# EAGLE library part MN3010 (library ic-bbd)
Dual 512-Stage Lo Noise BBD
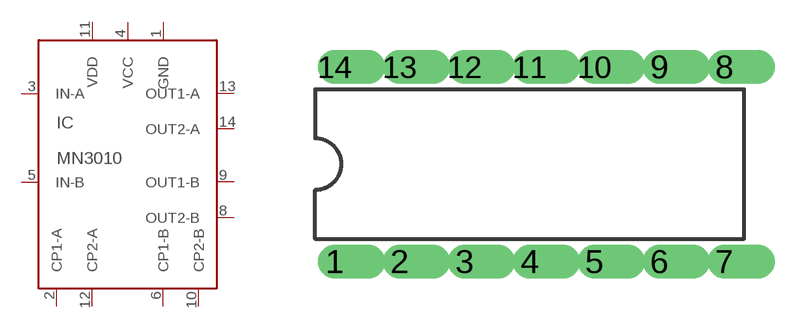
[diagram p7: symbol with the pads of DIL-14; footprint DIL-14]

Designator prefix IC

## MN3010  [DIL-14]
1  GND
2  CP1-A
3  IN-A
4  VCC
5  IN-B
6  CP1-B
8  OUT2-B
9  OUT1-B
10  CP2-B
11  VDD
12  CP2-A
13  OUT1-A
14  OUT2-A

## Footprint DIL-14 (pad centres in mm)
Dual In Line Package
drill 0.813 offset: 1 -7.62,-3.81; 2 -5.08,-3.81; 3 -2.54,-3.81; 4 0,-3.81; 5 2.54,-3.81; 6 5.08,-3.81; 7 7.62,-3.81; 8 7.62,3.81; 9 5.08,3.81; 10 2.54,3.81; 11 0,3.81; 12 -2.54,3.81; 13 -5.08,3.81; 14 -7.62,3.81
